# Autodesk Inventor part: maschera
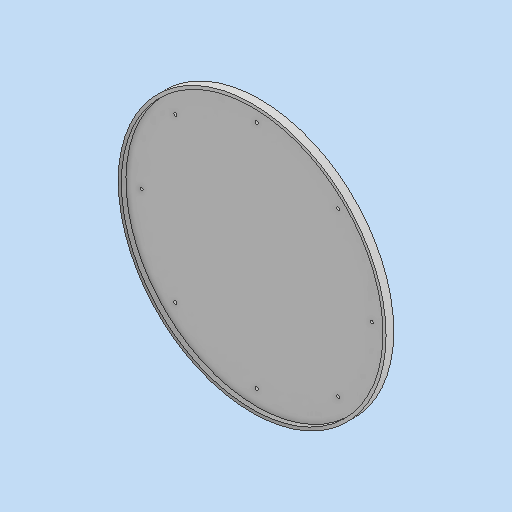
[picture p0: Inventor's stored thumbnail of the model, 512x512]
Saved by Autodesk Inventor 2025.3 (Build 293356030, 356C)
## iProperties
Created: 2026-02
Part Number: maschera
Material: Generico
Document SubType Name: Modeling
Designer: R5800u
Density: 1 g/cm^3
Appearance: Default
Author: R5800u
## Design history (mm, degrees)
node "Piano di lavoro1"
sketch "Schizzo1"
  geometry: C1 r 2.65 at (42.034, -62.114) reference; C2 r 2.65 at (73.644, -14.199) reference; C3 r 2.65 at (62.114, 42.034) reference; C4 r 2.65 at (14.199, 73.644) reference; C5 r 2.65 at (-42.034, 62.114) reference; C6 r 2.65 at (-73.644, 14.199) reference; C7 r 2.65 at (-62.114, -42.034) reference; C8 r 2.65 at (-14.199, -73.644) reference; C9 r 85 at (0, 0) reference; C10 r 85.2 at (0, 0); 1 further point
  constraints: 1 centre point
  dimensions: "d2" = 0.2 radial gap between concentric circles of C9 C10
extrude "Estrusione1" new body sketch "Schizzo1" distance "d0" = 2; taper "d1" = 0 deg
sketch "Schizzo2"
  geometry: C1 r 2.65 at (75, 0) reference; 2 further points
hole "Foro1" sketch "Schizzo2" at (75, 0) diameter "d3" = 2; stored, may be unused: countersink angle "d7" = 90 deg, drill point angle "d9" = 118 deg; dims "d4" = 6, "d5" = 12, "d6" = 5.7, "d8" = 8
pattern_circular "Serie circolare1" dims angle "d11" = 360 deg
sketch "Schizzo3"
  geometry: C1 r 85.2 at (0, 0) reference; C2 r 87.2 at (0, 0); 1 further point
  constraints: 1 centre point
  dimensions: "d13" = 2 radial gap between concentric circles of C1 C2
extrude "Estrusione2" join sketch "Schizzo3" distance "d14" = 5; taper "d15" = 0 deg
node "Solido1"
node "Riferimento1"
